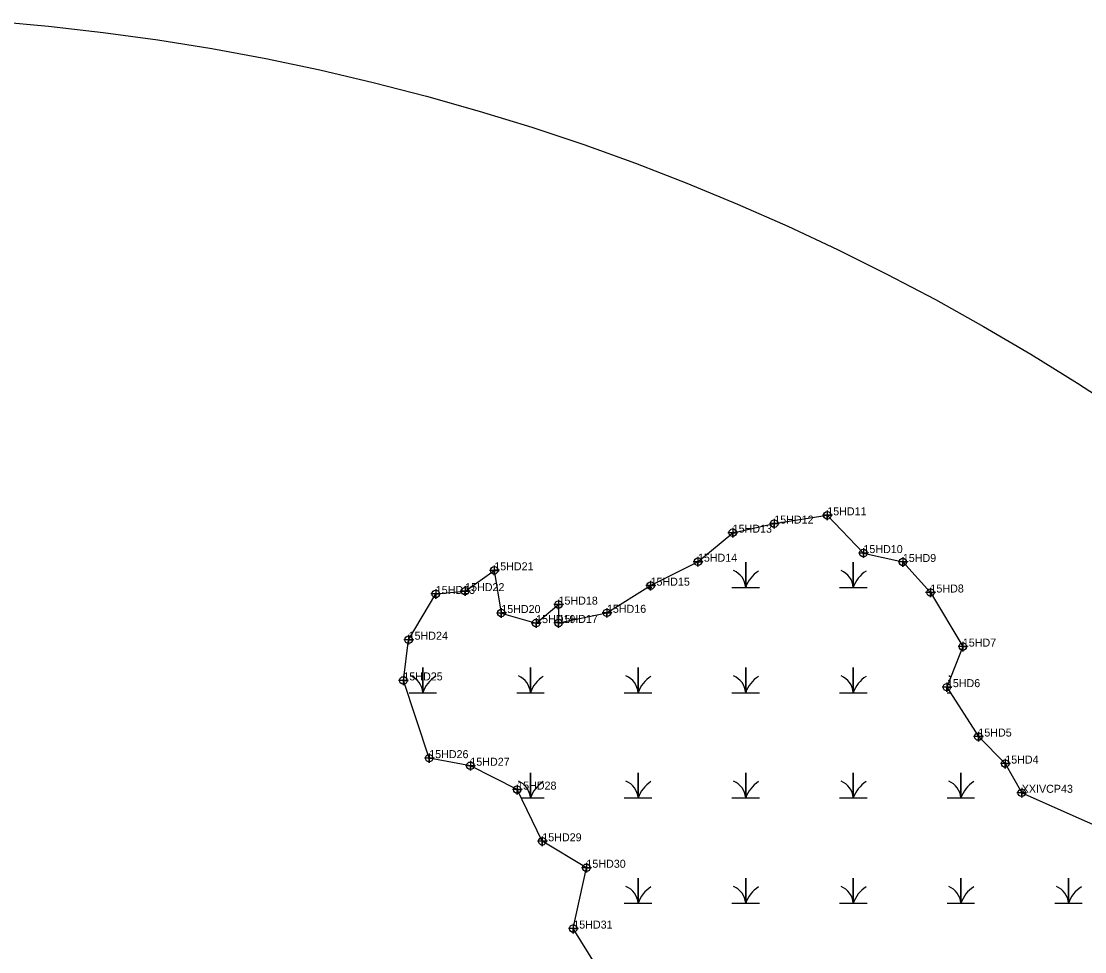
# Model space of a CAD drawing. Extents: x 2071991 to 2268989, y 436479 to 469629.
# Drawn here: x 2266870 to 2267534, y 444054 to 444635 of the extents above; entities that cross this region are included whole.
import ezdxf

# ---------------------------------------------------------------- set-up
doc = ezdxf.new("R2010")
doc.units = 0
for name, color, linetype in [('approx_PSA', 7, 'Continuous'), ('Exist Environmental Wetland Boundary', 7, 'Continuous'), ('Exist Environmental Wetland Boundary Cogo Comment', 7, 'Continuous'), ('Exist Environmental Wetland Boundary Cogo Point CELL', 7, 'Continuous'), ('Exist Hydro Swamp or Marsh', 7, 'Continuous')]:
    doc.layers.add(name, color=color, linetype=linetype)

msp = doc.modelspace()

# ---------------------------------------------------------------- linework, layer by layer
at = {"layer": 'approx_PSA'}
for p, q in [((2266853.23, 444635.38), (2266887.4, 444632.3)), ((2266887.4, 444632.3), (2266921.5, 444628.42)), ((2266921.5, 444628.42), (2266955.5, 444623.75)), ((2266955.5, 444623.75), (2266989.38, 444618.29)), ((2266989.38, 444618.29), (2267023.12, 444612.04)), ((2267023.12, 444612.04), (2267056.71, 444605.02)), ((2267056.71, 444605.02), (2267090.12, 444597.21)), ((2267090.12, 444597.21), (2267123.35, 444588.63)), ((2267123.35, 444588.63), (2267156.37, 444579.28)), ((2267156.37, 444579.28), (2267189.16, 444569.17)), ((2267189.16, 444569.17), (2267221.71, 444558.29)), ((2267221.71, 444558.29), (2267253.99, 444546.67)), ((2267253.99, 444546.67), (2267286, 444534.29)), ((2267286, 444534.29), (2267317.71, 444521.18)), ((2267317.71, 444521.18), (2267349.11, 444507.33)), ((2267349.11, 444507.33), (2267380.18, 444492.75)), ((2267380.18, 444492.75), (2267410.9, 444477.46)), ((2267410.9, 444477.46), (2267441.25, 444461.46)), ((2267441.25, 444461.46), (2267471.23, 444444.76)), ((2267471.23, 444444.76), (2267500.81, 444427.36)), ((2267500.81, 444427.36), (2267529.98, 444409.28)), ((2267529.98, 444409.28), (2267558.72, 444390.53))]:
    msp.add_line(p, q, dxfattribs=at)
at = {"layer": 'Exist Environmental Wetland Boundary'}
msp.add_lwpolyline([(2267238.96, 444029.98), (2267215.07, 444068.53), (2267223.27, 444106.54), (2267195.73, 444123.07), (2267180.03, 444155.38), (2267150.79, 444170.27), (2267125.08, 444175.01), (2267108.95, 444223.58), (2267112.23, 444249), (2267129.18, 444277.63), (2267147.51, 444279.34), (2267165.7, 444292.35), (2267170.08, 444265.69), (2267191.85, 444259.39), (2267205.85, 444270.93), (2267205.86, 444259.5), (2267236.05, 444265.81), (2267263.32, 444282.78), (2267292.89, 444297.74), (2267314.62, 444315.88), (2267340.6, 444321.55), (2267373.68, 444326.72), (2267396.26, 444303.14), (2267420.87, 444297.57), (2267438.13, 444278.5), (2267458.35, 444244.71), (2267448.38, 444219.37), (2267468.06, 444188.5), (2267484.83, 444171.6), (2267495.13, 444153.37), (2267576.76, 444117.09)], dxfattribs=at)
at = {"layer": 'Exist Environmental Wetland Boundary Cogo Point CELL'}
for points in [[(2267373.68, 444329.72), (2267373.68, 444323.72), (2267373.68, 444326.72), (2267376.68, 444326.72), (2267370.68, 444326.72)], [(2267340.6, 444324.55), (2267340.6, 444318.55), (2267340.6, 444321.55), (2267343.6, 444321.55), (2267337.6, 444321.55)], [(2267314.62, 444318.88), (2267314.62, 444312.88), (2267314.62, 444315.88), (2267317.62, 444315.88), (2267311.62, 444315.88)], [(2267292.89, 444300.74), (2267292.89, 444294.74), (2267292.89, 444297.74), (2267295.89, 444297.74), (2267289.89, 444297.74)], [(2267396.26, 444306.14), (2267396.26, 444300.14), (2267396.26, 444303.14), (2267399.26, 444303.14), (2267393.26, 444303.14)], [(2267420.87, 444300.57), (2267420.87, 444294.57), (2267420.87, 444297.57), (2267423.87, 444297.57), (2267417.87, 444297.57)], [(2267165.7, 444295.35), (2267165.7, 444289.35), (2267165.7, 444292.35), (2267168.7, 444292.35), (2267162.7, 444292.35)], [(2267129.18, 444280.63), (2267129.18, 444274.63), (2267129.18, 444277.63), (2267132.18, 444277.63), (2267126.18, 444277.63)], [(2267147.51, 444282.34), (2267147.51, 444276.34), (2267147.51, 444279.34), (2267150.51, 444279.34), (2267144.51, 444279.34)], [(2267263.32, 444285.78), (2267263.32, 444279.78), (2267263.32, 444282.78), (2267266.32, 444282.78), (2267260.32, 444282.78)], [(2267438.13, 444281.5), (2267438.13, 444275.5), (2267438.13, 444278.5), (2267441.13, 444278.5), (2267435.13, 444278.5)], [(2267205.85, 444273.93), (2267205.85, 444267.93), (2267205.85, 444270.93), (2267208.85, 444270.93), (2267202.85, 444270.93)], [(2267170.08, 444268.69), (2267170.08, 444262.69), (2267170.08, 444265.69), (2267173.08, 444265.69), (2267167.08, 444265.69)], [(2267236.05, 444268.81), (2267236.05, 444262.81), (2267236.05, 444265.81), (2267239.05, 444265.81), (2267233.05, 444265.81)], [(2267191.85, 444262.39), (2267191.85, 444256.39), (2267191.85, 444259.39), (2267194.85, 444259.39), (2267188.85, 444259.39)], [(2267205.86, 444262.5), (2267205.86, 444256.5), (2267205.86, 444259.5), (2267208.86, 444259.5), (2267202.86, 444259.5)], [(2267112.23, 444252), (2267112.23, 444246), (2267112.23, 444249), (2267115.23, 444249), (2267109.23, 444249)], [(2267458.35, 444247.71), (2267458.35, 444241.71), (2267458.35, 444244.71), (2267461.35, 444244.71), (2267455.35, 444244.71)], [(2267108.95, 444226.58), (2267108.95, 444220.58), (2267108.95, 444223.58), (2267111.95, 444223.58), (2267105.95, 444223.58)], [(2267448.38, 444222.37), (2267448.38, 444216.37), (2267448.38, 444219.37), (2267451.38, 444219.37), (2267445.38, 444219.37)], [(2267468.06, 444191.5), (2267468.06, 444185.5), (2267468.06, 444188.5), (2267471.06, 444188.5), (2267465.06, 444188.5)], [(2267125.08, 444178.01), (2267125.08, 444172.01), (2267125.08, 444175.01), (2267128.08, 444175.01), (2267122.08, 444175.01)], [(2267484.83, 444174.6), (2267484.83, 444168.6), (2267484.83, 444171.6), (2267487.83, 444171.6), (2267481.83, 444171.6)], [(2267150.79, 444173.27), (2267150.79, 444167.27), (2267150.79, 444170.27), (2267153.79, 444170.27), (2267147.79, 444170.27)], [(2267180.03, 444158.38), (2267180.03, 444152.38), (2267180.03, 444155.38), (2267183.03, 444155.38), (2267177.03, 444155.38)], [(2267495.13, 444156.37), (2267495.13, 444150.37), (2267495.13, 444153.37), (2267498.13, 444153.37), (2267492.13, 444153.37)], [(2267195.73, 444126.07), (2267195.73, 444120.07), (2267195.73, 444123.07), (2267198.73, 444123.07), (2267192.73, 444123.07)], [(2267223.27, 444109.54), (2267223.27, 444103.54), (2267223.27, 444106.54), (2267226.27, 444106.54), (2267220.27, 444106.54)], [(2267215.07, 444071.53), (2267215.07, 444065.53), (2267215.07, 444068.53), (2267218.07, 444068.53), (2267212.07, 444068.53)]]:
    msp.add_lwpolyline(points, dxfattribs=at)
for centre in [(2267373.68, 444326.72), (2267340.6, 444321.55), (2267314.62, 444315.88), (2267292.89, 444297.74), (2267396.26, 444303.14), (2267420.87, 444297.57), (2267165.7, 444292.35), (2267129.18, 444277.63), (2267147.51, 444279.34), (2267263.32, 444282.78), (2267438.13, 444278.5), (2267205.85, 444270.93), (2267170.08, 444265.69), (2267236.05, 444265.81), (2267191.85, 444259.39), (2267205.86, 444259.5), (2267112.23, 444249), (2267458.35, 444244.71), (2267108.95, 444223.58), (2267448.38, 444219.37), (2267468.06, 444188.5), (2267125.08, 444175.01), (2267484.83, 444171.6), (2267150.79, 444170.27), (2267180.03, 444155.38), (2267495.13, 444153.37), (2267195.73, 444123.07), (2267223.27, 444106.54), (2267215.07, 444068.53)]:
    msp.add_circle(centre, 2.34, dxfattribs=at)
at = {"layer": 'Exist Hydro Swamp or Marsh'}
for p, q in [((2267261.56, 444281.69), (2267264.13, 444281.69)), ((2267448.54, 444215.91), (2267450.58, 444215.91))]:
    msp.add_line(p, q, dxfattribs=at)
for points in [[(2267314.13, 444281.69), (2267322.74, 444281.69), (2267322.74, 444297.47), (2267322.74, 444281.69), (2267331.34, 444281.69)], [(2267381.34, 444281.69), (2267389.94, 444281.69), (2267389.94, 444297.47), (2267389.94, 444281.69), (2267398.54, 444281.69)], [(2267112.52, 444215.91), (2267121.13, 444215.91), (2267121.13, 444231.69), (2267121.13, 444215.91), (2267129.73, 444215.91)], [(2267179.73, 444215.91), (2267188.33, 444215.91), (2267188.33, 444231.69), (2267188.33, 444215.91), (2267196.93, 444215.91)], [(2267246.93, 444215.91), (2267255.53, 444215.91), (2267255.53, 444231.69), (2267255.53, 444215.91), (2267264.13, 444215.91)], [(2267314.13, 444215.91), (2267322.74, 444215.91), (2267322.74, 444231.69), (2267322.74, 444215.91), (2267331.34, 444215.91)], [(2267381.34, 444215.91), (2267389.94, 444215.91), (2267389.94, 444231.69), (2267389.94, 444215.91), (2267398.54, 444215.91)], [(2267182.58, 444150.13), (2267188.33, 444150.13), (2267188.33, 444165.91), (2267188.33, 444150.13), (2267196.93, 444150.13)], [(2267246.93, 444150.13), (2267255.53, 444150.13), (2267255.53, 444165.91), (2267255.53, 444150.13), (2267264.13, 444150.13)], [(2267314.13, 444150.13), (2267322.74, 444150.13), (2267322.74, 444165.91), (2267322.74, 444150.13), (2267331.34, 444150.13)], [(2267381.34, 444150.13), (2267389.94, 444150.13), (2267389.94, 444165.91), (2267389.94, 444150.13), (2267398.54, 444150.13)], [(2267448.54, 444150.13), (2267457.14, 444150.13), (2267457.14, 444165.91), (2267457.14, 444150.13), (2267465.74, 444150.13)], [(2267246.93, 444084.35), (2267255.53, 444084.35), (2267255.53, 444100.13), (2267255.53, 444084.35), (2267264.13, 444084.35)], [(2267314.13, 444084.35), (2267322.74, 444084.35), (2267322.74, 444100.13), (2267322.74, 444084.35), (2267331.34, 444084.35)], [(2267381.34, 444084.35), (2267389.94, 444084.35), (2267389.94, 444100.13), (2267389.94, 444084.35), (2267398.54, 444084.35)], [(2267448.54, 444084.35), (2267457.14, 444084.35), (2267457.14, 444100.13), (2267457.14, 444084.35), (2267465.74, 444084.35)], [(2267515.74, 444084.35), (2267524.35, 444084.35), (2267524.35, 444100.13), (2267524.35, 444084.35), (2267532.95, 444084.35)]]:
    msp.add_lwpolyline(points, dxfattribs=at)
for centre, radius, start, end in [((2267310.47, 444280.8), 12.3, 4.14034, 67.53497), ((2267340.98, 444275.63), 19.22, 122.12745, 161.62219), ((2267377.67, 444280.8), 12.3, 4.14034, 67.53497), ((2267408.18, 444275.63), 19.22, 122.12745, 161.62219), ((2267108.86, 444215.02), 12.3, 4.14034, 67.53497), ((2267139.37, 444209.85), 19.22, 122.12745, 161.62219), ((2267176.06, 444215.02), 12.3, 4.14034, 67.53497), ((2267206.57, 444209.85), 19.22, 122.12745, 161.62219), ((2267243.27, 444215.02), 12.3, 4.14034, 67.53497), ((2267273.77, 444209.85), 19.22, 122.12745, 161.62219), ((2267310.47, 444215.02), 12.3, 4.14034, 67.53497), ((2267340.98, 444209.85), 19.22, 122.12745, 161.62219), ((2267377.67, 444215.02), 12.3, 4.14034, 67.53497), ((2267408.18, 444209.85), 19.22, 122.12745, 161.62219), ((2267444.88, 444215.02), 12.3, 60.73926, 67.53497), ((2267176.06, 444149.24), 12.3, 4.14034, 67.53497), ((2267206.57, 444144.07), 19.22, 122.12745, 161.62219), ((2267243.27, 444149.24), 12.3, 4.14034, 67.53497), ((2267273.77, 444144.07), 19.22, 122.12745, 161.62219), ((2267310.47, 444149.24), 12.3, 4.14034, 67.53497), ((2267340.98, 444144.07), 19.22, 122.12745, 161.62219), ((2267377.67, 444149.24), 12.3, 4.14034, 67.53497), ((2267408.18, 444144.07), 19.22, 122.12745, 161.62219), ((2267444.88, 444149.24), 12.3, 4.14034, 67.53497), ((2267475.38, 444144.07), 19.22, 122.12745, 161.62219), ((2267243.27, 444083.46), 12.3, 4.14034, 67.53497), ((2267273.77, 444078.29), 19.22, 122.12745, 161.62219), ((2267310.47, 444083.46), 12.3, 4.14034, 67.53497), ((2267340.98, 444078.29), 19.22, 122.12745, 161.62219), ((2267377.67, 444083.46), 12.3, 4.14034, 67.53497), ((2267408.18, 444078.29), 19.22, 122.12745, 161.62219), ((2267444.88, 444083.46), 12.3, 4.14034, 67.53497), ((2267475.38, 444078.29), 19.22, 122.12745, 161.62219), ((2267512.08, 444083.46), 12.3, 4.14034, 67.53497), ((2267542.59, 444078.29), 19.22, 122.12745, 161.62219)]:
    msp.add_arc(centre, radius, start, end, dxfattribs=at)

# ---------------------------------------------------------------- texts
at = {"layer": 'Exist Environmental Wetland Boundary Cogo Comment'}
for s, p in [('15HD12', (2267340.6, 444321.55)), ('15HD11', (2267373.68, 444326.72)), ('15HD13', (2267314.62, 444315.88)), ('15HD10', (2267396.26, 444303.14)), ('15HD14', (2267292.89, 444297.74)), ('15HD9', (2267420.87, 444297.57)), ('15HD21', (2267165.7, 444292.35)), ('15HD15', (2267263.32, 444282.78)), ('15HD23', (2267129.18, 444277.63)), ('15HD22', (2267147.51, 444279.34)), ('15HD8', (2267438.13, 444278.5)), ('15HD18', (2267205.85, 444270.93)), ('15HD20', (2267170.08, 444265.69)), ('15HD16', (2267236.05, 444265.81)), ('15HD19', (2267191.85, 444259.39)), ('15HD17', (2267205.86, 444259.5)), ('15HD24', (2267112.23, 444249)), ('15HD7', (2267458.35, 444244.71)), ('15HD25', (2267108.95, 444223.58)), ('15HD6', (2267448.38, 444219.37)), ('15HD5', (2267468.06, 444188.5)), ('15HD26', (2267125.08, 444175.01)), ('15HD27', (2267150.79, 444170.27)), ('15HD4', (2267484.83, 444171.6)), ('15HD28', (2267180.03, 444155.38)), ('XXIVCP43 ', (2267495.13, 444153.37)), ('15HD29', (2267195.73, 444123.07)), ('15HD30', (2267223.27, 444106.54)), ('15HD31', (2267215.07, 444068.53))]:
    msp.add_text(s, height=5, dxfattribs=at).set_placement(p)

doc.saveas('drawing.dxf')
